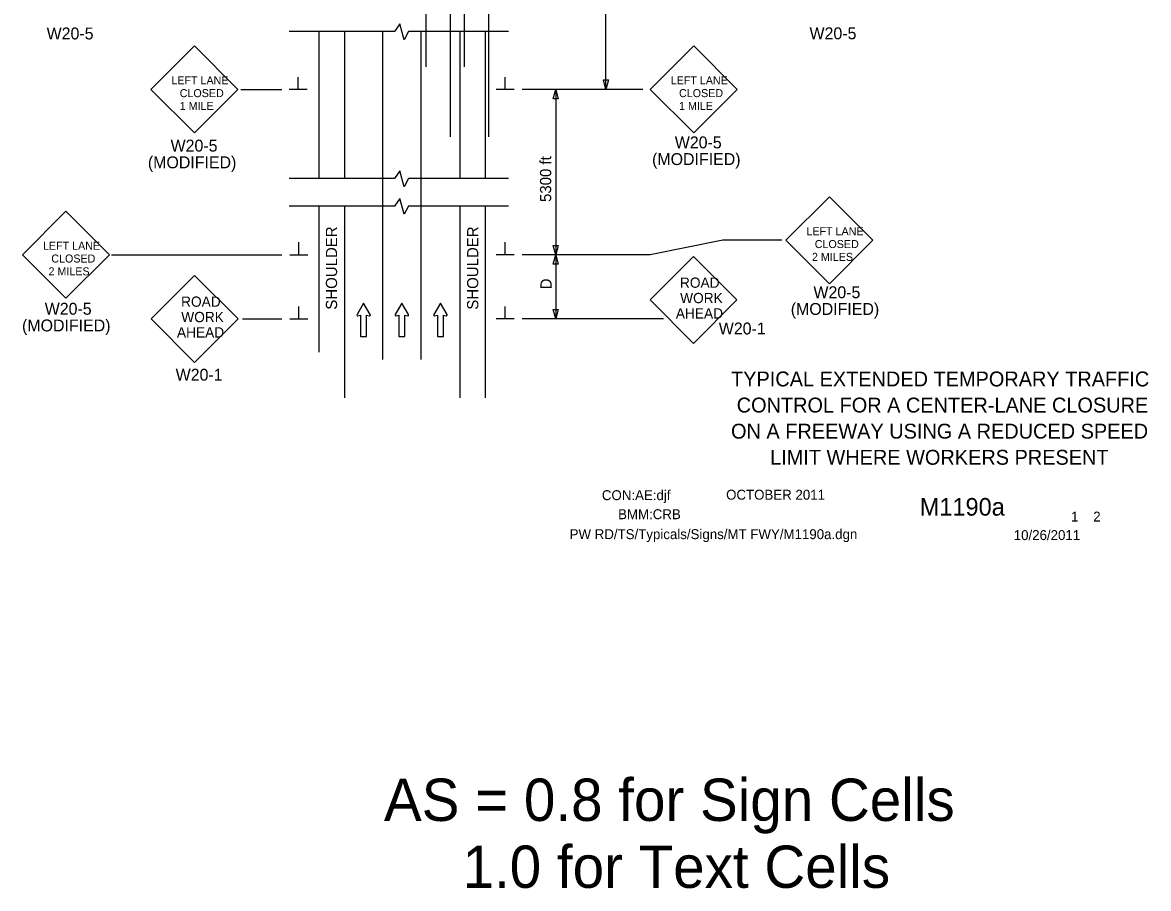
# Model space of a CAD drawing. Extents: x 16729 to 18482, y 7002 to 8333.
# Drawn here: x 16729 to 17432, y 7002 to 7543 of the extents above; entities that cross this region are included whole.
import ezdxf

# ---------------------------------------------------------------- set-up
doc = ezdxf.new("R2010")
doc.units = 0
for name, color, linetype in [('ALI_LEGAL_EX', 7, 'Continuous'), ('BORDER', 7, 'Continuous'), ('BORDER_SIGNAL_WO', 7, 'Continuous'), ('MT_SCRATCH_LEVEL_E', 7, 'Continuous'), ('PAVT_EDGE_EX', 7, 'Continuous'), ('TRAFFIC_SIGNS_PR', 7, 'Continuous'), ('TYPICAL_TEXT_DIMEN_PR', 7, 'Continuous')]:
    doc.layers.add(name, color=color, linetype=linetype)

msp = doc.modelspace()

# ---------------------------------------------------------------- linework, layer by layer
at = {"layer": 'ALI_LEGAL_EX'}
for p, q in [((16980.68, 8333.08), (16980.68, 7514.94)), ((17004.68, 8333.08), (17004.68, 7514.94)), ((16995.95, 8289.26), (16995.95, 7471.12)), ((17019.95, 8289.26), (17019.95, 7471.12)), ((16953.87, 7450.01), (16953.87, 7527.17)), ((16977.87, 7450.01), (16977.87, 7527.17)), ((16953.87, 7332.07), (16953.87, 7512.88)), ((16977.87, 7332.07), (16977.87, 7512.88))]:
    msp.add_line(p, q, dxfattribs=at)
for points in [[(16953.87, 7527.42), (16953.87, 7536.81)], [(16977.87, 7527.42), (16977.87, 7536.81)], [(16953.87, 7445.04), (16953.87, 7452.42)], [(16977.87, 7445.04), (16977.87, 7452.42)], [(16953.87, 7361.48), (16953.87, 7386.48)], [(16977.87, 7361.48), (16977.87, 7386.48)]]:
    msp.add_lwpolyline(points, dxfattribs=at)
at = {"layer": 'MT_SCRATCH_LEVEL_E'}
for p, q in [((16941.87, 7367.36), (16937.75, 7360.12)), ((16946.01, 7360.12), (16941.87, 7367.36)), ((16965.77, 7367.36), (16961.66, 7360.12)), ((16969.92, 7360.12), (16965.77, 7367.36)), ((16989.82, 7367.36), (16985.71, 7360.12)), ((16993.97, 7360.12), (16989.82, 7367.36)), ((16938.24, 7359.44), (16940.01, 7359.75)), ((16940.01, 7359.75), (16940.01, 7346.5)), ((16943.76, 7346.5), (16943.76, 7359.75)), ((16943.76, 7359.75), (16945.53, 7359.44)), ((16962.14, 7359.44), (16963.92, 7359.75)), ((16963.92, 7359.75), (16963.92, 7346.5)), ((16967.66, 7346.5), (16967.66, 7359.75)), ((16967.66, 7359.75), (16969.44, 7359.44)), ((16986.19, 7359.44), (16987.97, 7359.75)), ((16987.97, 7359.75), (16987.97, 7346.5)), ((16991.71, 7346.5), (16991.71, 7359.75)), ((16991.71, 7359.75), (16993.49, 7359.44)), ((16940.01, 7346.5), (16943.76, 7346.5)), ((16963.92, 7346.5), (16967.66, 7346.5)), ((16987.97, 7346.5), (16991.71, 7346.5))]:
    msp.add_line(p, q, dxfattribs=at)
for centre, start, end in [((16938.16, 7359.9), 150.42484, 279.96381), ((16945.6, 7359.9), 260.03619, 29.77312), ((16962.07, 7359.9), 150.42484, 279.96381), ((16969.51, 7359.9), 260.03619, 29.77312), ((16986.12, 7359.9), 150.42484, 279.96381), ((16993.56, 7359.9), 260.03619, 29.77312)]:
    msp.add_arc(centre, 0.463, start, end, dxfattribs=at)
at = {"layer": 'PAVT_EDGE_EX'}
for p, q in [((16913.87, 7536.81), (16913.87, 7445.04)), ((16929.87, 7536.81), (16929.87, 7445.04)), ((17001.87, 7536.81), (17001.87, 7445.04)), ((17017.87, 7536.81), (17017.87, 7445.04)), ((16913.87, 7427.91), (16913.87, 7336.73)), ((16929.87, 7427.91), (16929.87, 7308.25)), ((17001.87, 7427.91), (17001.87, 7308.25)), ((17017.87, 7427.91), (17017.87, 7308.25))]:
    msp.add_line(p, q, dxfattribs=at)
at = {"layer": 'TRAFFIC_SIGNS_PR'}
for p, q in [((16836.16, 7527.92), (16809.01, 7500.77)), ((16863.32, 7500.77), (16836.16, 7527.92)), ((17148.04, 7527.92), (17120.89, 7500.77)), ((17175.2, 7500.77), (17148.04, 7527.92)), ((16809.01, 7500.77), (16836.16, 7473.62)), ((16836.16, 7473.62), (16863.32, 7500.77)), ((17120.89, 7500.77), (17148.04, 7473.62)), ((17148.04, 7473.62), (17175.2, 7500.77)), ((17232.82, 7433.69), (17205.67, 7406.53)), ((17259.97, 7406.53), (17232.82, 7433.69)), ((16755.96, 7424.65), (16728.81, 7397.49)), ((16783.12, 7397.49), (16755.96, 7424.65)), ((17205.67, 7406.53), (17232.82, 7379.38)), ((17232.82, 7379.38), (17259.97, 7406.53)), ((16728.81, 7397.49), (16755.96, 7370.34)), ((16755.96, 7370.34), (16783.12, 7397.49)), ((17147.92, 7396.5), (17120.77, 7369.35)), ((17175.07, 7369.35), (17147.92, 7396.5)), ((16836.31, 7384.65), (16809.15, 7357.49)), ((16863.46, 7357.49), (16836.31, 7384.65)), ((17120.77, 7369.35), (17147.92, 7342.2)), ((17147.92, 7342.2), (17175.07, 7369.35)), ((16809.15, 7357.49), (16836.31, 7330.34)), ((16836.31, 7330.34), (16863.46, 7357.49))]:
    msp.add_line(p, q, dxfattribs=at)
at = {"layer": 'TYPICAL_TEXT_DIMEN_PR'}
for p, q in [((17093.18, 7500.77), (17093.18, 7770.57)), ((16964.47, 7541.61), (16961.21, 7536.81)), ((16967.21, 7531.67), (16964.47, 7541.61)), ((16961.21, 7536.81), (16895.27, 7536.81)), ((16969.95, 7536.81), (16967.21, 7531.67)), ((17032.29, 7536.81), (16969.95, 7536.81)), ((16900.96, 7500.66), (16900.96, 7508.45)), ((17030.24, 7500.66), (17030.24, 7508.45)), ((17093.18, 7500.77), (17091.61, 7506.63)), ((17091.61, 7506.63), (17093.18, 7506.63)), ((17093.18, 7506.63), (17094.75, 7506.63)), ((17094.75, 7506.63), (17093.18, 7500.77)), ((16865.18, 7500.77), (16890.87, 7500.77)), ((16906.59, 7500.66), (16895.34, 7500.66)), ((17035.87, 7500.66), (17024.62, 7500.66)), ((17116.28, 7500.77), (17040.87, 7500.77)), ((17060.3, 7494.91), (17061.87, 7500.77)), ((17061.87, 7500.77), (17061.87, 7397.49)), ((17061.87, 7500.77), (17063.44, 7494.91)), ((17061.87, 7494.91), (17060.3, 7494.91)), ((17063.44, 7494.91), (17061.87, 7494.91)), ((16964.47, 7449.84), (16961.21, 7445.04)), ((16967.21, 7439.9), (16964.47, 7449.84)), ((16961.21, 7445.04), (16895.27, 7445.04)), ((16969.95, 7445.04), (16967.21, 7439.9)), ((17032.29, 7445.04), (16969.95, 7445.04)), ((16961.21, 7427.91), (16895.27, 7427.91)), ((16964.47, 7432.71), (16961.21, 7427.91)), ((16967.21, 7422.77), (16964.47, 7432.71)), ((16969.95, 7427.91), (16967.21, 7422.77)), ((17032.29, 7427.91), (16969.95, 7427.91)), ((17166.25, 7406.53), (17120.83, 7397.49)), ((17203.12, 7406.53), (17166.25, 7406.53)), ((16901.49, 7397.49), (16901.49, 7405.28)), ((17030.24, 7397.49), (17030.24, 7405.28)), ((17061.87, 7397.49), (17060.3, 7403.35)), ((17060.3, 7403.35), (17061.87, 7403.35)), ((17061.87, 7403.35), (17063.44, 7403.35)), ((17063.44, 7403.35), (17061.87, 7397.49)), ((16784.42, 7397.49), (16890.87, 7397.49)), ((16895.87, 7397.49), (16907.12, 7397.49)), ((17035.87, 7397.49), (17024.62, 7397.49)), ((17120.83, 7397.49), (17040.87, 7397.49)), ((17060.3, 7391.63), (17061.87, 7397.49)), ((17061.87, 7391.63), (17060.3, 7391.63)), ((17061.87, 7397.49), (17061.87, 7357.49)), ((17061.87, 7397.49), (17063.44, 7391.63)), ((17063.44, 7391.63), (17061.87, 7391.63)), ((16901.49, 7357.49), (16901.49, 7365.28)), ((17030.24, 7357.49), (17030.24, 7365.28)), ((16866.26, 7357.49), (16890.87, 7357.49)), ((16895.87, 7357.49), (16907.12, 7357.49)), ((17035.87, 7357.49), (17024.62, 7357.49)), ((17129.08, 7357.49), (17040.87, 7357.49)), ((17061.87, 7357.49), (17060.3, 7363.35)), ((17060.3, 7363.35), (17061.87, 7363.35)), ((17061.87, 7363.35), (17063.44, 7363.35)), ((17063.44, 7363.35), (17061.87, 7357.49))]:
    msp.add_line(p, q, dxfattribs=at)

# ---------------------------------------------------------------- texts
at = {"layer": 'BORDER'}
for s, p in [('TYPICAL EXTENDED TEMPORARY TRAFFIC', (17171.38, 7315.31)), ('CONTROL FOR A CENTER-LANE CLOSURE', (17174.9, 7299.01)), ('ON A FREEWAY USING A REDUCED SPEED', (17171.36, 7282.71)), ('LIMIT WHERE WORKERS PRESENT', (17195.75, 7266.41))]:
    msp.add_text(s, height=9.3, dxfattribs=at).set_placement(p)
at = {"layer": 'BORDER_SIGNAL_WO'}
for s, height, p in [('CON:AE:djf  ', 6.2, (17090.69, 7244.31)), ('    OCTOBER 2011    ', 6.2, (17159.08, 7244.59)), ('    M1190a   ', 11, (17272.86, 7234.63)), ('BMM:CRB   ', 6.2, (17100.81, 7232.42)), (' 1    2 ', 6.2, (17381.45, 7230.95)), ('PW RD/TS/Typicals/Signs/MT FWY/M1190a.dgn      ', 6.2, (17070.55, 7219.96)), ('10/26/2011    ', 6.2, (17347.93, 7219.38)), ('AS = 0.8 for Sign Cells', 26.4241, (16954.57, 7044.01)), ('     1.0 for Text Cells', 26.4241, (16954.57, 7002.22))]:
    msp.add_text(s, height=height, dxfattribs=at).set_placement(p)
at = {"layer": 'TRAFFIC_SIGNS_PR'}
for s, height, p in [('W20-5', 7.44, (16743.87, 7531.96)), ('W20-5', 7.44, (17220.38, 7532.05)), ('LEFT LANE', 5, (16821.79, 7503.92)), ('LEFT LANE', 5, (17133.67, 7503.92)), ('CLOSED', 5, (16827, 7495.92)), ('CLOSED', 5, (17138.88, 7495.92)), ('1 MILE', 5, (16827, 7487.93)), ('1 MILE', 5, (17138.88, 7487.93)), ('W20-5', 7.44, (16821.3, 7461.93)), ('W20-5', 7.44, (17136.22, 7463.95)), ('(MODIFIED)', 7.44, (16807.12, 7451.49)), ('(MODIFIED)', 7.44, (17122.04, 7453.51)), ('LEFT LANE', 5, (17218.45, 7409.69)), ('LEFT LANE', 5, (16741.59, 7400.65)), ('CLOSED', 5, (17223.66, 7401.69)), ('2 MILES', 5, (17221.91, 7393.69)), ('CLOSED', 5, (16746.8, 7392.65)), ('2 MILES', 5, (16745.05, 7384.65)), ('ROAD', 6.4, (17139.46, 7376.89)), ('W20-5', 7.44, (17222.83, 7370.38)), ('ROAD', 6.4, (16827.85, 7365.03)), ('WORK', 6.4, (17139.57, 7367.29)), ('W20-5', 7.44, (16742.69, 7360.08)), ('AHEAD', 6.4, (17136.88, 7357.69)), ('(MODIFIED)', 7.44, (17208.65, 7359.94)), ('(MODIFIED)', 7.44, (16728.51, 7349.64)), ('WORK', 6.4, (16827.96, 7355.43)), ('AHEAD', 6.4, (16825.27, 7345.83)), ('W20-1', 7.44, (17163.7, 7347.75)), ('W20-1', 7.44, (16824.47, 7318.9))]:
    msp.add_text(s, height=height, dxfattribs=at).set_placement(p)
at = {"layer": 'TYPICAL_TEXT_DIMEN_PR'}
for s, p in [('5300 ft', (17059.02, 7430.44)), ('SHOULDER', (16925.29, 7363.2)), ('SHOULDER', (17013.49, 7363.2)), ('D', (17059.31, 7375.91))]:
    msp.add_text(s, height=7, rotation=90, dxfattribs=at).set_placement(p)

doc.saveas('drawing.dxf')
